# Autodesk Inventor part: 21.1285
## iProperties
Created: 2006-02
Part Number: 21.1285
Material: Steel, Mild
Description: M4x30 SHCS
Document SubType Name: Modeling
Standard: DIN 7984
Designer: Andy Moles
Standards Organization: DIN
Language: en-US
Size Designation: M4 x 16
Categories: <MemberInstance><Categories><Category DisplayName="Fasteners" InternalName="e4da775c-781d-43d5-af7c-5136215cf5a6" Mnemonic="FSTN"><Category DisplayName="Bolts"
Density: 7.86 g/cm^3
Mass: 2.30133 g
Surface Area: 3.5375 cm^2
Volume: 0.29279 cm^3
Author: Andy Moles
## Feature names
1. Body [Revolution]
2. Slot [Extrusion]
3. Fillet1
4. Chamfer1
